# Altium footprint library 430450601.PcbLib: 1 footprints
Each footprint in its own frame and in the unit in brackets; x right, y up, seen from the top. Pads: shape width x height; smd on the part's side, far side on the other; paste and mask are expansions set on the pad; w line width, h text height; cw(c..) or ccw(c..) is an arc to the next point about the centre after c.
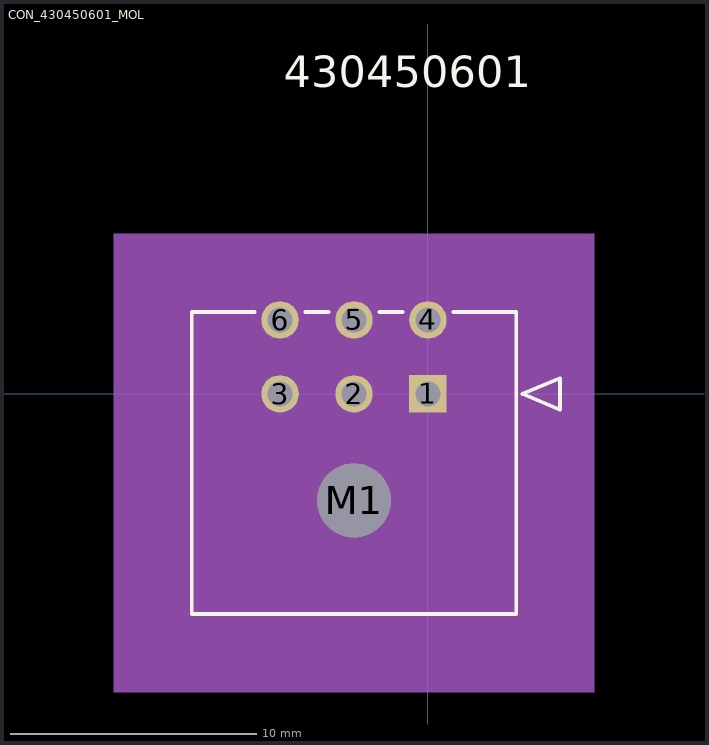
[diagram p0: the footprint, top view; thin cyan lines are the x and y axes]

## CON_430450601_MOL [mm]
pads (7):
  rect 1.52x1.52 hole 1.02 mask+0.076: 1(0,0)
  round 1.52 hole 1.02 mask+0.076: 2(-3,0) 3(-6,0) 4(0,3) 5(-3,3) 6(-6,3)
  round 3 hole 3 unplated mask+0.076: M1(-3,-4.32)
Top Overlay:
  lines w0.152: -7.032,3.32 -9.575,3.32 -9.575,-8.92 3.575,-8.92 3.575,3.32 1.032,3.32 ; -4.968,3.32 -4.032,3.32 ; -1.968,3.32 -1.032,3.32 ; 3.829,0 5.353,0.635 5.353,-0.635 3.829,0
  text "430450601" at -5.858,12.44 h1.27
Mechanical 3:
  text "PTH_DRILL_SIZE:_1.02_MM,_TOLERANCE:_+0.05/-0.05" at -17.923,-15.5 h1.27
  text "NPTH_DRILL_SIZE:_3.0_MM,_TOLERANCE:_+0.05/-0.05" at -17.923,-18.04 h1.27
Mechanical 5:
  region: -12.75,6.495 6.75,6.495 6.75,-12.095 -12.75,-12.095
Mechanical 10:
  text "PTH_DRILL_SIZE:_1.02_MM,_TOLERANCE:_+0.05/-0.05" at -17.923,-15.5 h1.27
  text "NPTH_DRILL_SIZE:_3.0_MM,_TOLERANCE:_+0.05/-0.05" at -17.923,-18.04 h1.27
Mechanical 13:
  lines w0.127: -9.575,-8.92 3.575,-8.92 3.575,3.32 -9.575,3.32 -9.575,-8.92 ; 3.829,0 5.353,0.635 5.353,-0.635 3.829,0
  text "430450601" at -5.858,12.44 h1.27
Mechanical 15:
  region: 4.845,4.59 -10.845,4.59 -10.845,-10.19 4.845,-10.19
  lines w0.127: -10.845,-10.19 -10.845,4.59 4.845,4.59 4.845,-10.19 -10.845,-10.19
3D body: height 0.25, standoff 0, extent 0,0 0.254,0.254
3D body "430450601.stp": height 8.78, standoff -3.17, extent -9.575,-8.92 3.575,3.32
